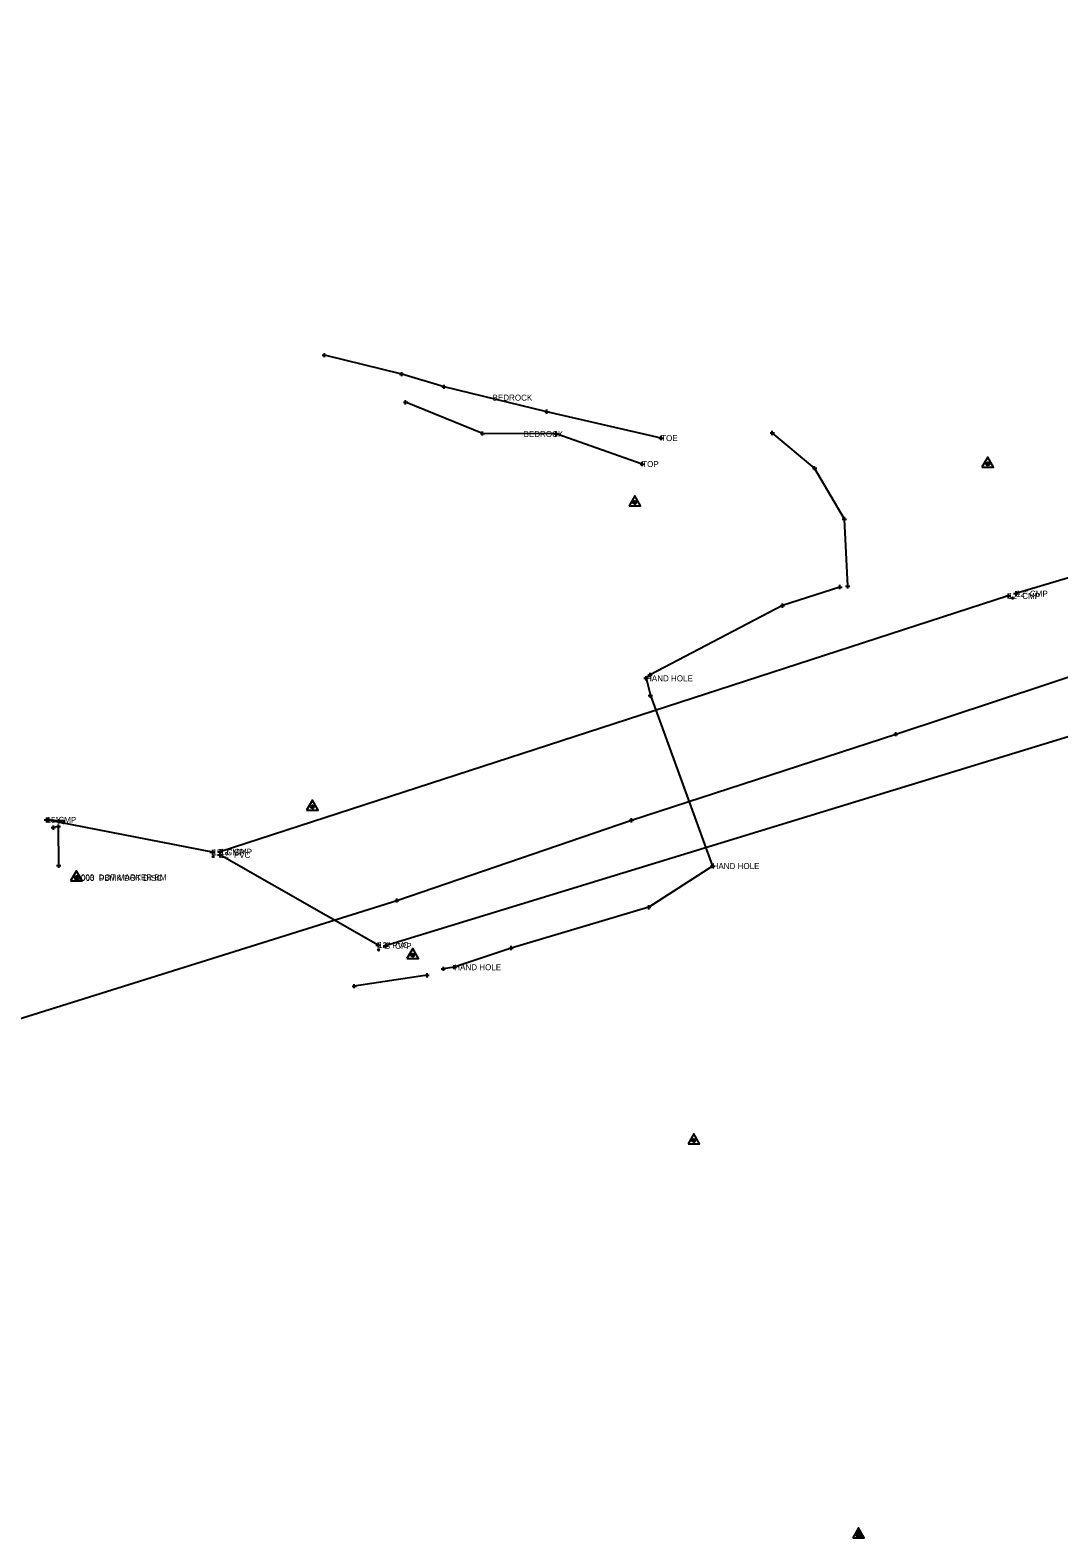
# Model space of a CAD drawing. Extents: x 1729655 to 1739338, y 463812 to 469501.
# Drawn here: x 1735596.9 to 1735905.4, y 466852.7 to 467304.7 of the extents above; entities that cross this region are included whole.
import ezdxf

# ---------------------------------------------------------------- set-up
doc = ezdxf.new("R2010")
doc.units = 0
for name, color, linetype in [('Default', 7, 'Continuous'), ('S_Bridge_Abutment_Bottom', 7, 'Continuous'), ('S_Bridge_Column_Round', 7, 'Continuous'), ('S_Bridge_ExpansionJoint', 7, 'Continuous'), ('S_Buildings_Steps', 7, 'Continuous'), ('S_Control_Temp_Traverse', 7, 'Continuous'), ('S_Drainage_Sump', 7, 'Continuous'), ('S_RetWall_Top', 7, 'Continuous'), ('S_Roadway_Bedrock_Outcrop', 7, 'Continuous'), ('S_Survey_Shot', 7, 'Continuous'), ('S_Terrain_Boundary', 7, 'Continuous'), ('S_Terrain_Breaklines', 7, 'Continuous'), ('S_Terrain_High_Points', 7, 'Continuous'), ('S_Terrain_Imported_Contours', 7, 'Continuous'), ('S_Terrain_Voids', 7, 'Continuous'), ('S_Text', 7, 'Continuous'), ('S_Utilities_Pole_Power', 7, 'Continuous'), ('S_Utilities_Pole_StreetLight', 7, 'Continuous')]:
    doc.layers.add(name, color=color, linetype=linetype)

msp = doc.modelspace()

# ---------------------------------------------------------------- linework, layer by layer
at = {"layer": 'Default'}
msp.add_line((1735601.86, 467067.96), (1735601.86, 467067.96), dxfattribs=at)
at = {"layer": 'S_Bridge_Abutment_Bottom'}
for p, q in [((1735610.39, 467050.12), (1735610.79, 467050.91)), ((1735611.18, 467050.12), (1735610.39, 467050.12)), ((1735610.47, 467049.96), (1735610.86, 467050.75)), ((1735611.25, 467049.96), (1735610.47, 467049.96)), ((1735610.79, 467050.91), (1735611.18, 467050.12)), ((1735610.79, 467050.91), (1735610.79, 467050.71)), ((1735610.86, 467050.75), (1735611.25, 467049.96)), ((1735610.86, 467050.75), (1735610.86, 467050.55))]:
    msp.add_line(p, q, dxfattribs=at)
at = {"layer": 'S_Bridge_Column_Round'}
for p, q in [((1735685.15, 467206.63), (1735685.15, 467207.91)), ((1735684.51, 467207.27), (1735685.79, 467207.27)), ((1735685.15, 467207.27), (1735685.15, 467207.27)), ((1735707.7, 467201.57), (1735708.97, 467201.57)), ((1735708.34, 467200.93), (1735708.33, 467202.2)), ((1735708.34, 467201.57), (1735708.34, 467201.57)), ((1735720.39, 467197.77), (1735721.66, 467197.77)), ((1735721.03, 467197.14), (1735721.02, 467198.41)), ((1735721.02, 467197.77), (1735721.02, 467197.77)), ((1735708.87, 467193.15), (1735710.14, 467193.16)), ((1735709.51, 467192.52), (1735709.5, 467193.79)), ((1735709.51, 467193.15), (1735709.51, 467193.15)), ((1735751.23, 467190.3), (1735752.51, 467190.3)), ((1735751.87, 467189.66), (1735751.87, 467190.93)), ((1735751.87, 467190.3), (1735751.87, 467190.3)), ((1735731.93, 467183.77), (1735733.21, 467183.78)), ((1735732.57, 467183.14), (1735732.57, 467184.41)), ((1735732.57, 467183.77), (1735732.57, 467183.77)), ((1735753.99, 467183.66), (1735755.26, 467183.66)), ((1735754.62, 467183.03), (1735754.62, 467184.3)), ((1735754.62, 467183.66), (1735754.62, 467183.66)), ((1735785.48, 467182.4), (1735786.75, 467182.4)), ((1735786.12, 467181.77), (1735786.12, 467183.04)), ((1735786.12, 467182.4), (1735786.12, 467182.4)), ((1735818.82, 467183.95), (1735820.09, 467183.96)), ((1735819.46, 467183.32), (1735819.45, 467184.59)), ((1735819.45, 467183.96), (1735819.45, 467183.96)), ((1735779.82, 467174.62), (1735781.09, 467174.63)), ((1735780.45, 467173.99), (1735780.45, 467175.26)), ((1735780.45, 467174.62), (1735780.45, 467174.62)), ((1735831.5, 467173.39), (1735832.77, 467173.39)), ((1735832.13, 467172.75), (1735832.13, 467174.03)), ((1735832.13, 467173.39), (1735832.13, 467173.39)), ((1735840.42, 467158.12), (1735841.69, 467158.13)), ((1735841.05, 467157.49), (1735841.05, 467158.76)), ((1735841.05, 467158.13), (1735841.05, 467158.13)), ((1735839.1, 467137.73), (1735840.37, 467137.74)), ((1735839.73, 467137.1), (1735839.73, 467138.37)), ((1735839.73, 467137.73), (1735839.73, 467137.73)), ((1735841.44, 467137.99), (1735842.71, 467138)), ((1735842.07, 467137.36), (1735842.07, 467138.63)), ((1735842.07, 467138), (1735842.07, 467138)), ((1735821.87, 467132.21), (1735823.14, 467132.21)), ((1735822.51, 467131.57), (1735822.51, 467132.85)), ((1735822.51, 467132.21), (1735822.51, 467132.21)), ((1735780.96, 467110.39), (1735782.23, 467110.39)), ((1735781.6, 467109.75), (1735781.59, 467111.03)), ((1735781.59, 467110.39), (1735781.59, 467110.39)), ((1735782.16, 467111.39), (1735783.43, 467111.39)), ((1735782.79, 467110.75), (1735782.79, 467112.03)), ((1735782.79, 467111.39), (1735782.79, 467111.39)), ((1735782.28, 467105.2), (1735783.55, 467105.2)), ((1735782.92, 467104.56), (1735782.92, 467105.83)), ((1735782.92, 467105.2), (1735782.92, 467105.2)), ((1735855.86, 467093.65), (1735857.13, 467093.65)), ((1735856.5, 467093.01), (1735856.49, 467094.29)), ((1735856.5, 467093.65), (1735856.5, 467093.65)), ((1735601.94, 467067.98), (1735603.21, 467067.98)), ((1735602.58, 467067.34), (1735602.57, 467068.61)), ((1735602.58, 467067.98), (1735602.58, 467067.98)), ((1735604.87, 467067.52), (1735606.14, 467067.53)), ((1735604.87, 467067.52), (1735606.14, 467067.53)), ((1735605.5, 467066.89), (1735605.5, 467068.16)), ((1735605.5, 467066.89), (1735605.5, 467068.16)), ((1735605.5, 467067.52), (1735605.5, 467067.52)), ((1735605.5, 467067.52), (1735605.5, 467067.52)), ((1735776.58, 467067.85), (1735777.86, 467067.86)), ((1735777.22, 467067.22), (1735777.22, 467068.49)), ((1735777.22, 467067.85), (1735777.22, 467067.85)), ((1735603.28, 467065.65), (1735604.55, 467065.65)), ((1735603.92, 467065.01), (1735603.92, 467066.29)), ((1735603.92, 467065.65), (1735603.92, 467065.65)), ((1735604.78, 467065.95), (1735606.05, 467065.96)), ((1735605.42, 467065.32), (1735605.41, 467066.59)), ((1735605.41, 467065.96), (1735605.41, 467065.96)), ((1735604.85, 467054.25), (1735606.12, 467054.25)), ((1735605.49, 467053.61), (1735605.49, 467054.88)), ((1735605.49, 467054.25), (1735605.49, 467054.25)), ((1735800.92, 467054.12), (1735802.19, 467054.12)), ((1735801.56, 467053.49), (1735801.56, 467054.76)), ((1735801.56, 467054.12), (1735801.56, 467054.12)), ((1735706.24, 467043.79), (1735707.51, 467043.8)), ((1735706.87, 467043.16), (1735706.87, 467044.43)), ((1735706.87, 467043.8), (1735706.87, 467043.8)), ((1735781.8, 467041.76), (1735783.07, 467041.76)), ((1735782.43, 467041.13), (1735782.43, 467042.4)), ((1735782.43, 467041.76), (1735782.43, 467041.76)), ((1735740.49, 467029.55), (1735741.76, 467029.55)), ((1735741.12, 467028.92), (1735741.12, 467030.19)), ((1735741.12, 467029.55), (1735741.12, 467029.55)), ((1735720.2, 467023.32), (1735721.48, 467023.32)), ((1735720.84, 467022.68), (1735720.84, 467023.95)), ((1735720.84, 467023.32), (1735720.84, 467023.32)), ((1735723.48, 467023.8), (1735724.75, 467023.8)), ((1735724.11, 467023.17), (1735724.11, 467024.44)), ((1735724.11, 467023.8), (1735724.11, 467023.8)), ((1735693.46, 467018.1), (1735694.74, 467018.1)), ((1735694.1, 467017.47), (1735694.1, 467018.74)), ((1735694.1, 467018.1), (1735694.1, 467018.1)), ((1735715.32, 467021.39), (1735716.59, 467021.39)), ((1735715.95, 467020.75), (1735715.95, 467022.03)), ((1735715.95, 467021.39), (1735715.95, 467021.39))]:
    msp.add_line(p, q, dxfattribs=at)
at = {"layer": 'S_Bridge_ExpansionJoint'}
for p, q in [((1735890.21, 467135.83), (1735890.21, 467134.33)), ((1735891.75, 467135.8), (1735893.25, 467135.8)), ((1735892.5, 467136.55), (1735892.5, 467135.05)), ((1735889.46, 467135.08), (1735890.96, 467135.08)), ((1735601.11, 467067.96), (1735602.61, 467067.96)), ((1735601.86, 467068.71), (1735601.86, 467067.21)), ((1735651.59, 467059), (1735651.59, 467057.5)), ((1735653.16, 467058.39), (1735654.66, 467058.39)), ((1735653.91, 467059.14), (1735653.91, 467057.64)), ((1735650.84, 467058.25), (1735652.34, 467058.25)), ((1735653.06, 467057.43), (1735654.56, 467057.43)), ((1735653.81, 467058.18), (1735653.81, 467056.68)), ((1735700.54, 467030.42), (1735702.04, 467030.42)), ((1735701.29, 467031.17), (1735701.29, 467029.67)), ((1735702.73, 467030.18), (1735704.23, 467030.18)), ((1735703.48, 467030.93), (1735703.48, 467029.43))]:
    msp.add_line(p, q, dxfattribs=at)
at = {"layer": 'S_Buildings_Steps'}
for p, q in [((1735781.99, 467110.39), (1735781.2, 467110.39)), ((1735781.86, 467110.13), (1735781.33, 467110.65)), ((1735781.86, 467110.65), (1735781.33, 467110.13)), ((1735781.59, 467110.78), (1735781.59, 467110)), ((1735801.95, 467054.12), (1735801.17, 467054.12)), ((1735801.82, 467053.86), (1735801.3, 467054.38)), ((1735801.82, 467054.38), (1735801.3, 467053.86)), ((1735801.56, 467054.52), (1735801.56, 467053.73)), ((1735724.51, 467023.8), (1735723.72, 467023.8)), ((1735724.38, 467023.54), (1735723.85, 467024.07)), ((1735724.38, 467024.07), (1735723.85, 467023.54)), ((1735724.11, 467024.2), (1735724.11, 467023.41))]:
    msp.add_line(p, q, dxfattribs=at)
at = {"layer": 'S_Control_Temp_Traverse'}
for p, q in [((1735883.91, 467174.67), (1735884.16, 467174.67)), ((1735884.03, 467174.79), (1735884.03, 467174.54)), ((1735778.09, 467163.13), (1735778.34, 467163.13)), ((1735778.22, 467163.25), (1735778.22, 467163)), ((1735795.79, 466971.89), (1735796.04, 466971.89)), ((1735795.92, 466972.02), (1735795.92, 466971.77))]:
    msp.add_line(p, q, dxfattribs=at)
for points in [[(1735882.3, 467173.67), (1735885.76, 467173.67), (1735884.03, 467176.66)], [(1735776.49, 467162.13), (1735779.94, 467162.13), (1735778.22, 467165.12)], [(1735794.19, 466970.89), (1735797.64, 466970.89), (1735795.92, 466973.89)]]:
    msp.add_lwpolyline(points, close=True, dxfattribs=at)
for centre in [(1735884.03, 467174.67), (1735778.22, 467163.13), (1735795.92, 466971.89)]:
    msp.add_circle(centre, 0.499, dxfattribs=at)
at = {"layer": 'S_Drainage_Sump'}
for p, q in [((1735891.82, 467134.43), (1735891.03, 467134.43)), ((1735891.69, 467134.17), (1735891.17, 467134.69)), ((1735891.69, 467134.69), (1735891.17, 467134.17)), ((1735891.43, 467134.83), (1735891.43, 467134.04)), ((1735652.18, 467056.93), (1735651.39, 467056.93)), ((1735652.05, 467056.67), (1735651.52, 467057.19)), ((1735652.05, 467057.19), (1735651.52, 467056.67)), ((1735651.78, 467057.32), (1735651.78, 467056.54)), ((1735701.77, 467028.97), (1735700.99, 467028.97)), ((1735701.64, 467028.71), (1735701.12, 467029.23)), ((1735701.64, 467029.23), (1735701.12, 467028.71)), ((1735701.38, 467029.36), (1735701.38, 467028.57))]:
    msp.add_line(p, q, dxfattribs=at)
at = {"layer": 'S_RetWall_Top'}
for p, q in [((1736046.34, 467182.16), (1735892.5, 467135.8)), ((1735890.21, 467135.08), (1735653.91, 467058.39)), ((1735916.16, 467095.31), (1735703.48, 467030.18)), ((1735651.59, 467058.25), (1735601.86, 467067.96)), ((1735602.58, 467067.98), (1735605.5, 467067.52)), ((1735701.29, 467030.42), (1735653.81, 467057.43))]:
    msp.add_line(p, q, dxfattribs=at)
msp.add_lwpolyline([(1735602.58, 467067.98), (1735605.5, 467067.52)], dxfattribs=at)
at = {"layer": 'S_Roadway_Bedrock_Outcrop'}
for points in [[(1735786.12, 467182.4), (1735751.87, 467190.3), (1735721.02, 467197.77), (1735708.34, 467201.57), (1735685.15, 467207.27)], [(1735780.45, 467174.62), (1735754.62, 467183.66), (1735732.57, 467183.77), (1735709.51, 467193.15)]]:
    msp.add_lwpolyline(points, dxfattribs=at)
at = {"layer": 'S_Survey_Shot'}
msp.add_lwpolyline([(1735327.94, 466925.11), (1735706.87, 467043.8), (1735777.22, 467067.85), (1735856.5, 467093.65), (1735947.31, 467123.71), (1736072.24, 467163.39), (1736148.46, 467186.6), (1736188.58, 467199.8), (1736250.41, 467218.61), (1736341.55, 467246.49), (1736425.62, 467273.68), (1736484.8, 467292.24), (1736522.29, 467304.69), (1736527.82, 467289.35)], dxfattribs=at)
at = {"layer": 'S_Terrain_Boundary'}
for p, q in [((1735845.19, 466853.73), (1735845.44, 466853.73)), ((1735845.31, 466853.85), (1735845.31, 466853.61))]:
    msp.add_line(p, q, dxfattribs=at)
msp.add_lwpolyline([(1735843.59, 466852.73), (1735847.04, 466852.73), (1735845.31, 466855.73)], close=True, dxfattribs=at)
msp.add_circle((1735845.31, 466853.73), 0.499, dxfattribs=at)
at = {"layer": 'S_Terrain_Breaklines'}
msp.add_line((1735604.04, 467067.75), (1735604.04, 467067.75), dxfattribs=at)
msp.add_lwpolyline([(1735604.04, 467067.75), (1735607.04, 467067.74), (1735606.9, 467066.86)], close=True, dxfattribs=at)
at = {"layer": 'S_Terrain_Imported_Contours'}
msp.add_line((1735845.31, 466853.73), (1735845.31, 466853.73), dxfattribs=at)
msp.add_lwpolyline([(1735844.45, 466853.23), (1735845.31, 466854.73), (1735846.18, 466853.23)], close=True, dxfattribs=at)
msp.add_circle((1735845.31, 466853.73), 0.5, dxfattribs=at)
at = {"layer": 'S_Terrain_Voids'}
for p, q in [((1735681.54, 467072), (1735681.54, 467071.75)), ((1735681.42, 467071.88), (1735681.67, 467071.88)), ((1735711.51, 467027.43), (1735711.75, 467027.43)), ((1735711.63, 467027.55), (1735711.63, 467027.3))]:
    msp.add_line(p, q, dxfattribs=at)
for points in [[(1735679.81, 467070.88), (1735683.27, 467070.88), (1735681.54, 467073.87)], [(1735709.9, 467026.43), (1735713.36, 467026.43), (1735711.63, 467029.42)]]:
    msp.add_lwpolyline(points, close=True, dxfattribs=at)
for centre in [(1735681.54, 467071.88), (1735711.63, 467027.43)]:
    msp.add_circle(centre, 0.499, dxfattribs=at)
at = {"layer": 'S_Text'}
for p, q in [((1735610.66, 467050.71), (1735610.91, 467050.71)), ((1735610.79, 467050.84), (1735610.79, 467050.59))]:
    msp.add_line(p, q, dxfattribs=at)
msp.add_lwpolyline([(1735609.06, 467049.71), (1735612.52, 467049.71), (1735610.79, 467052.71)], close=True, dxfattribs=at)
msp.add_circle((1735610.79, 467050.71), 0.499, dxfattribs=at)
at = {"layer": 'S_Utilities_Pole_Power'}
msp.add_lwpolyline([(1735605.49, 467054.25), (1735605.41, 467065.96), (1735603.92, 467065.65)], dxfattribs=at)
at = {"layer": 'S_Utilities_Pole_StreetLight'}
for points in [[(1735842.07, 467138), (1735841.05, 467158.13), (1735832.13, 467173.39), (1735819.45, 467183.96)], [(1735839.73, 467137.73), (1735822.51, 467132.21), (1735782.79, 467111.39), (1735781.59, 467110.39), (1735782.92, 467105.2), (1735801.56, 467054.12), (1735782.43, 467041.76), (1735741.12, 467029.55), (1735724.11, 467023.8), (1735720.84, 467023.32)], [(1735715.95, 467021.39), (1735694.1, 467018.1)]]:
    msp.add_lwpolyline(points, dxfattribs=at)

# ---------------------------------------------------------------- texts
at = {"layer": 'S_Terrain_High_Points'}
for s, p in [('BEDROCK', (1735735.58, 467193.63)), ('BEDROCK', (1735744.87, 467182.72)), ('TOE', (1735786.12, 467181.5)), ('TOP', (1735780.45, 467173.72)), ('12" CMP', (1735890.21, 467134.18)), ('12" CMP', (1735892.5, 467134.9)), ('HAND HOLE', (1735781.59, 467109.49)), ('HAND HOLE', (1735781.59, 467109.49)), ('15"CMP', (1735601.86, 467067.06)), ('15" CMP', (1735651.59, 467057.35)), ('12" CMP', (1735653.91, 467057.49)), ('12" PVC', (1735653.81, 467056.53)), ('HAND HOLE', (1735801.56, 467053.22)), ('HAND HOLE', (1735801.56, 467053.22)), ('8003', (1735610.79, 467049.81)), ('1000', (1735610.86, 467049.65)), ('DOT MARKER BM', (1735617.49, 467049.81)), ('PBMK DOT DISC', (1735617.56, 467049.65)), ('12" PVC', (1735701.29, 467029.52)), ('8" CPP', (1735703.48, 467029.28)), ('HAND HOLE', (1735724.11, 467022.9)), ('HAND HOLE', (1735724.11, 467022.9))]:
    msp.add_text(s, height=1.8, dxfattribs=at).set_placement(p)

doc.saveas('drawing.dxf')
